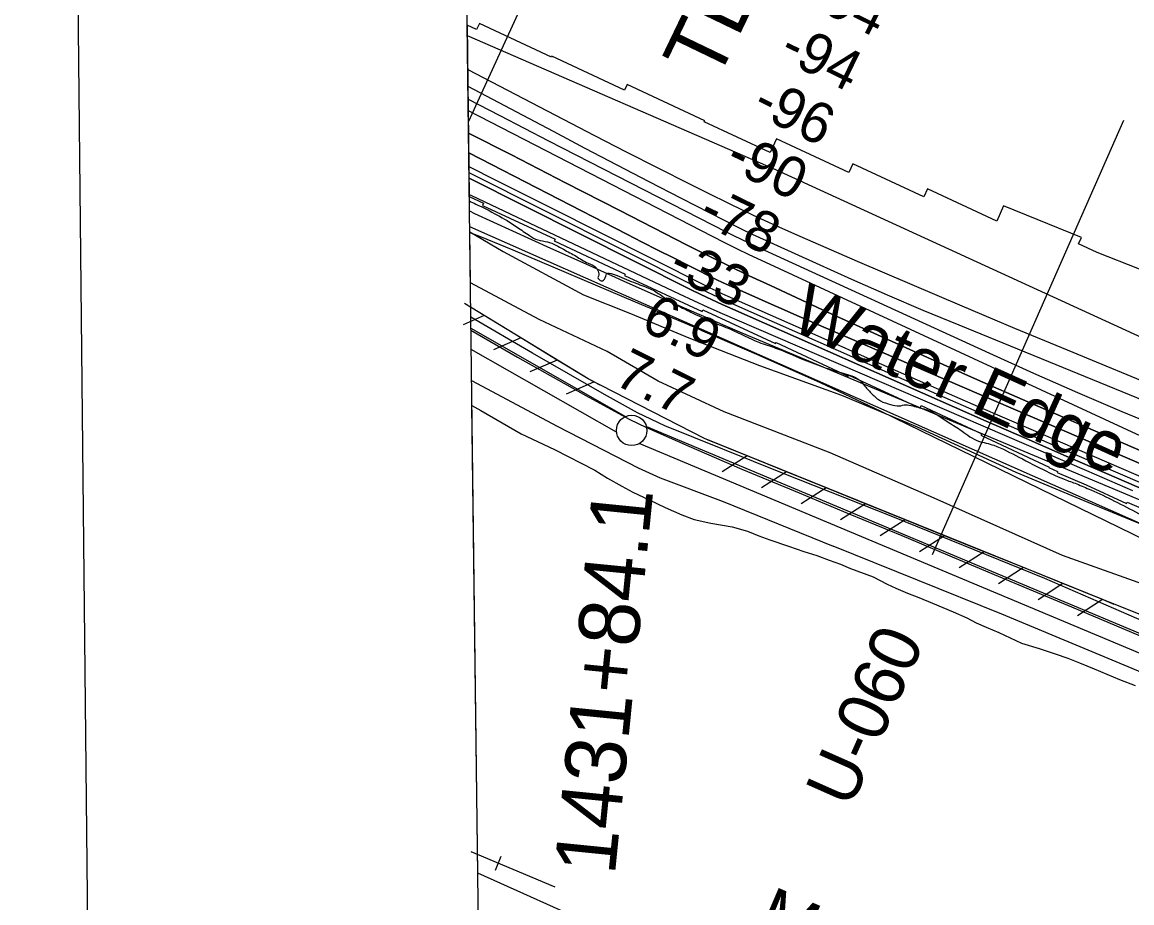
# Model space of a CAD drawing. Extents: x 3734862 to 3772949, y 391520 to 417239.
# Drawn here: x 3738202 to 3740026, y 405553 to 406999 of the extents above; entities that cross this region are included whole.
import ezdxf

# ---------------------------------------------------------------- set-up
doc = ezdxf.new("R2010")
doc.units = 0
for name, color, linetype in [('V-ANNO-SYMB', 7, 'Continuous'), ('V-CHAN-NAID', 7, 'Continuous'), ('V-FLOD-BASE', 7, 'Continuous'), ('V-GRID-FRAM', 7, 'Continuous'), ('V-LEVE-TOET', 7, 'Continuous'), ('V-RAIL-IDEN', 7, 'Continuous'), ('V-RAIL-TRAK', 7, 'Continuous'), ('V-RIVR-EDGE', 7, 'Continuous'), ('V-RIVR-IDEN', 7, 'Continuous'), ('V-RIVR-RANG', 7, 'Continuous'), ('V-RIVR-RANG-IDEN', 7, 'Continuous'), ('V-RRAP-FSHR', 7, 'Continuous'), ('V-RRAP-RVMT', 7, 'Continuous'), ('V-SITE-VEGE', 7, 'Continuous'), ('V-SURV-IDEN', 7, 'Continuous'), ('V-SURV-LINE', 7, 'Continuous'), ('V-TOPO-DPTH', 7, 'Continuous'), ('V-TOPO-MAJR', 7, 'Continuous'), ('V-TOPO-MINR', 7, 'Continuous'), ('V-TOPO-WATR', 7, 'Continuous')]:
    doc.layers.add(name, color=color, linetype=linetype)

msp = doc.modelspace()

# ---------------------------------------------------------------- linework, layer by layer
at = {"layer": 'V-ANNO-SYMB'}
msp.add_lwpolyline([(3738444.4, 392757.5), (3771525.7, 393106.9), (3771283.7, 416022.2), (3738202.3, 415672.8), (3738444.4, 392757.5)], dxfattribs=at)
at = {"layer": 'V-FLOD-BASE'}
msp.add_lwpolyline([(3738939.8, 406493.4), (3739016.1, 406448.9), (3739128.5, 406386), (3739199.5, 406346.9), (3739228.4, 406333.2), (3739297.9, 406302.6), (3739384.8, 406265.2), (3739478.9, 406226), (3739562.2, 406190.9), (3739648, 406156.1), (3739741.1, 406116.9), (3739833.6, 406077.7), (3739926.7, 406039.1), (3740025.4, 405997.5), (3740124.6, 405955.2)], dxfattribs=at)
at = {"layer": 'V-GRID-FRAM'}
msp.add_lwpolyline([(3738832.3, 415033.8), (3770599.2, 415447.4), (3770843.8, 397266.6), (3739061.1, 396852.8), (3738832.3, 415033.8)], dxfattribs=at)
at = {"layer": 'V-LEVE-TOET'}
for points in [[(3741628.7, 405352.2), (3741426.2, 405436.3), (3741222.6, 405521), (3741001.7, 405613.9), (3740778.7, 405706.8), (3740561.8, 405793.6), (3740300.3, 405903.7), (3740121.9, 405981.5), (3739882.5, 406085.3), (3739632.9, 406186.6), (3739451.9, 406258.3), (3739258.1, 406336.2), (3739213.5, 406357.5), (3739159.2, 406387.5), (3739040.8, 406455.3), (3738939.5, 406514.6)], [(3738940.8, 406410.9), (3739081.4, 406335.4), (3739214.6, 406267.1), (3739250.5, 406251), (3739354.1, 406212), (3739535.1, 406138.7)], [(3741503.1, 405309.1), (3741232, 405429.5), (3740957.7, 405546.3), (3740650.1, 405671.5), (3740361.5, 405794.5), (3740102.6, 405906.1), (3739811.9, 406027.1), (3739535.1, 406138.7)]]:
    msp.add_lwpolyline(points, dxfattribs=at)
at = {"layer": 'V-RAIL-TRAK'}
for points in [[(3739078, 405578.6), (3738939.9, 405636.7)], [(3738979.9, 405606.4), (3738989.6, 405629.4)]]:
    msp.add_lwpolyline(points, dxfattribs=at)
at = {"layer": 'V-RIVR-EDGE'}
msp.add_spline([(3738937.1, 406705.6), (3738947.7, 406700.5), (3739015.5, 406662.8), (3739036.1, 406648.6), (3739049.4, 406641.7), (3739065.6, 406638.4), (3739091.8, 406626.2), (3739112.4, 406614.8), (3739132.2, 406603.4), (3739146, 406595.3), (3739148.8, 406590.1), (3739149.2, 406582), (3739148.3, 406580), (3739150.4, 406576.7), (3739153.6, 406574.3), (3739157.6, 406575.5), (3739162.1, 406584.4), (3739163.3, 406586.4), (3739166.6, 406586.8), (3739179.9, 406583.1), (3739195.6, 406576.6), (3739210.6, 406570.5), (3739223.9, 406565.6), (3739243.7, 406556.3), (3739261.5, 406543.7), (3739278.8, 406533.9), (3739301.1, 406523), (3739336.6, 406506.7), (3739366.1, 406494.9), (3739412.9, 406473.4), (3739440.4, 406464), (3739478.8, 406448.1), (3739513.5, 406434.7), (3739547.5, 406423.7), (3739562, 406419.6), (3739576.2, 406413.1), (3739587, 406401.3), (3739599.1, 406388.4), (3739612.9, 406377), (3739629.4, 406371.3), (3739643.6, 406368.9), (3739654.1, 406370.9), (3739665.8, 406368.8), (3739687.2, 406363.1), (3739704.2, 406355.4), (3739724, 406342.4), (3739746.6, 406327.8), (3739773.6, 406311.1), (3739786.6, 406307.9), (3739798.7, 406304.2), (3739840.3, 406284.7), (3739885.5, 406261.5), (3739914.6, 406248.5), (3739935.2, 406240.8), (3739958.2, 406231), (3739997.4, 406212.7), (3740036.6, 406192.4), (3740070.1, 406176.1), (3740091.9, 406166), (3740122.6, 406155), (3740144.9, 406150.5), (3740162.6, 406145.6), (3740180.8, 406138.7), (3740205.9, 406128.9), (3740242.6, 406112.6), (3740284.2, 406091.5)], degree=3, dxfattribs=at)
at = {"layer": 'V-RIVR-RANG'}
for p, q in [((3738935.5, 406835.4), (3739084.1, 407158.7)), ((3739697.9, 406124.6), (3740012.4, 406838.4))]:
    msp.add_line(p, q, dxfattribs=at)
at = {"layer": 'V-RRAP-FSHR'}
for p, q in [((3738961.7, 406517.2), (3738927, 406501.9)), ((3739021.5, 406480.7), (3738976.8, 406461.1)), ((3739081.3, 406444.3), (3739036.6, 406424.7)), ((3739141.1, 406407.9), (3739096.3, 406388.3)), ((3739393.4, 406286.9), (3739352.4, 406260.4)), ((3739458.3, 406260.7), (3739417.3, 406234.1)), ((3739523.2, 406234.5), (3739482.2, 406207.9)), ((3739588.1, 406208.2), (3739547.1, 406181.7)), ((3739653, 406182), (3739612, 406155.4)), ((3739717.9, 406155.8), (3739676.9, 406129.2)), ((3739782.8, 406129.5), (3739741.8, 406103)), ((3739847.7, 406103.3), (3739806.7, 406076.7)), ((3739912.6, 406077.1), (3739871.6, 406050.5)), ((3739977.5, 406050.8), (3739936.5, 406024.3))]:
    msp.add_line(p, q, dxfattribs=at)
for points in [[(3738937.6, 406663.6), (3740052.6, 406170.3), (3741469, 405553.1)], [(3740004.8, 406039.8), (3739323.4, 406315.2), (3739132.3, 406413.3), (3738929, 406537.1)], [(3738961.7, 406517.2), (3738929, 406537.1)], [(3739021.5, 406480.7), (3738961.7, 406517.2)], [(3739081.3, 406444.3), (3739021.5, 406480.7)], [(3739141.4, 406408.6), (3739132.3, 406413.3), (3739081.3, 406444.3)], [(3739151.9, 406403.2), (3739141.4, 406408.6)], [(3739328.5, 406313.2), (3739323.4, 406315.2), (3739318, 406318)], [(3739393.4, 406286.9), (3739328.5, 406313.2)], [(3739458.3, 406260.7), (3739393.4, 406286.9)], [(3739523.2, 406234.5), (3739458.3, 406260.7)], [(3739588.1, 406208.2), (3739523.2, 406234.5)], [(3739653, 406182), (3739588.1, 406208.2)], [(3739717.9, 406155.8), (3739653, 406182)], [(3739782.8, 406129.5), (3739717.9, 406155.8)], [(3739847.7, 406103.3), (3739782.8, 406129.5)], [(3739912.6, 406077.1), (3739847.7, 406103.3)], [(3739977.5, 406050.8), (3739912.6, 406077.1)], [(3739996.9, 406043), (3739977.5, 406050.8)], [(3744483.7, 404317.7), (3744096.9, 404414.5), (3743639.2, 404531), (3743120.2, 404667), (3742731.1, 404762.5), (3742601.7, 404809.4), (3742448.9, 404910.7), (3742129.5, 405108.3), (3741905.3, 405240.5), (3741772.8, 405307.9), (3741598.8, 405383.1), (3741291.5, 405502.3), (3740610.8, 405791.5), (3740295.5, 405923.9), (3740004.8, 406039.8)]]:
    msp.add_lwpolyline(points, dxfattribs=at)
at = {"layer": 'V-RRAP-RVMT'}
for p, q in [((3738953.6, 406996.9), (3738949, 406987.1)), ((3739072.1, 406941.7), (3738953.6, 406996.9)), ((3738933.5, 406994.3), (3738937, 406712.7)), ((3738949, 406987.1), (3738933.5, 406994.3)), ((3739072.9, 406943.5), (3739072.1, 406941.7)), ((3739192.3, 406887.8), (3739072.9, 406943.5)), ((3739196.4, 406896.8), (3739192.3, 406887.8)), ((3739323.9, 406837.4), (3739196.4, 406896.8)), ((3739323, 406835.6), (3739323.9, 406837.4)), ((3739431.6, 406785), (3739323, 406835.6)), ((3739442, 406807.4), (3739431.6, 406785)), ((3739560.5, 406752.2), (3739442, 406807.4)), ((3739567.2, 406766.5), (3739560.5, 406752.2)), ((3739683.9, 406712.3), (3739567.2, 406766.5)), ((3739690.1, 406725.6), (3739683.9, 406712.3)), ((3739803.9, 406672.6), (3739690.1, 406725.6)), ((3738937, 406712.7), (3738960.3, 406701.9)), ((3738960.3, 406701.9), (3738958.6, 406698.2)), ((3738958.6, 406698.2), (3739078, 406642.6)), ((3739814.6, 406697.7), (3739803.9, 406672.6)), ((3739942.9, 406645.5), (3739814.6, 406697.7)), ((3739078, 406642.6), (3739076.7, 406639.9)), ((3739076.7, 406639.9), (3739193.4, 406585.5)), ((3739938.2, 406635.1), (3739942.9, 406645.5)), ((3739968.7, 406620.9), (3739938.2, 406635.1)), ((3740038.2, 406593.6), (3739968.7, 406620.9)), ((3739193.4, 406585.5), (3739192.3, 406583.3)), ((3739192.3, 406583.3), (3739319.6, 406523.9)), ((3739319.6, 406523.9), (3739321, 406526.8)), ((3739321, 406526.8), (3739440.2, 406471.3)), ((3739440.2, 406471.3), (3739441.1, 406473.2)), ((3739441.1, 406473.2), (3739559.8, 406417.9)), ((3739559.8, 406417.9), (3739560.6, 406419.6)), ((3739560.6, 406419.6), (3739677.7, 406365.1)), ((3739677.7, 406365.1), (3739679.8, 406369.5)), ((3739679.8, 406369.5), (3739779, 406323.3)), ((3739779, 406323.3), (3739777.8, 406320.8)), ((3739777.8, 406320.8), (3739890.1, 406268.5)), ((3739890.1, 406268.5), (3739889.6, 406267.6)), ((3739889.6, 406267.6), (3739903.8, 406261)), ((3739903.8, 406261), (3739903, 406259.3)), ((3739903, 406259.3), (3739950.6, 406239.2)), ((3739950.6, 406239.2), (3740016.7, 406208.4)), ((3740016.7, 406208.4), (3740017.8, 406210.8)), ((3740017.8, 406210.8), (3740063.1, 406191.6))]:
    msp.add_line(p, q, dxfattribs=at)
at = {"layer": 'V-SITE-VEGE'}
for p, q in [((3738938.8, 406571.2), (3738937.7, 406655)), ((3738937.7, 406655), (3738992.7, 406622.6)), ((3738992.7, 406622.6), (3739124.7, 406551.2)), ((3739052, 406511.1), (3738938.8, 406571.2)), ((3739124.7, 406551.2), (3739201.7, 406520.6)), ((3739163.4, 406458.2), (3739052, 406511.1)), ((3739201.7, 406520.6), (3739297.7, 406480.8)), ((3739297.7, 406480.8), (3739414, 406435.1)), ((3739247.4, 406409.5), (3739163.4, 406458.2)), ((3739414, 406435.1), (3739548.9, 406386.8)), ((3739356, 406359.2), (3739247.4, 406409.5)), ((3739548.9, 406386.8), (3739673.1, 406334.8)), ((3738951, 405601.4), (3738941.3, 406369.6)), ((3738941.3, 406369.6), (3738956.2, 406361.6)), ((3738956.2, 406361.6), (3738990.8, 406341.1)), ((3739530.1, 406291.6), (3739356, 406359.2)), ((3738990.8, 406341.1), (3739022, 406322.8)), ((3739022, 406322.8), (3739077.1, 406297.2)), ((3739673.1, 406334.8), (3739835.1, 406259.9)), ((3739077.1, 406297.2), (3739143.4, 406263.4)), ((3739700.9, 406217.3), (3739530.1, 406291.6)), ((3739143.4, 406263.4), (3739163.9, 406250.3)), ((3739163.9, 406250.3), (3739187.4, 406236.9)), ((3739835.1, 406259.9), (3739959.9, 406208)), ((3739187.4, 406236.9), (3739205.7, 406227.3)), ((3739205.7, 406227.3), (3739232.6, 406214.5)), ((3739232.6, 406214.5), (3739258.6, 406202.3)), ((3739912, 406123.1), (3739700.9, 406217.3)), ((3739258.6, 406202.3), (3739286, 406190.2)), ((3739959.9, 406208), (3740080.6, 406158.5)), ((3739286, 406190.2), (3739306.6, 406182.4)), ((3739306.6, 406182.4), (3739333.8, 406176.4)), ((3739333.8, 406176.4), (3739369.1, 406170.1)), ((3739369.1, 406170.1), (3739394.2, 406163)), ((3739394.2, 406163), (3739412.7, 406155.6)), ((3739412.7, 406155.6), (3739430.6, 406149)), ((3739430.6, 406149), (3739461.4, 406138.7)), ((3739461.4, 406138.7), (3739487, 406129.9)), ((3739487, 406129.9), (3739508.2, 406123)), ((3739508.2, 406123), (3739528.6, 406115.7)), ((3740099.9, 406056), (3739912, 406123.1)), ((3739528.6, 406115.7), (3739546.9, 406108.8)), ((3739546.9, 406108.8), (3739563.4, 406101.7)), ((3739563.4, 406101.7), (3739600.5, 406088.4)), ((3739600.5, 406088.4), (3739623.8, 406076.3)), ((3739623.8, 406076.3), (3739638, 406069.7)), ((3739638, 406069.7), (3739657, 406061.4)), ((3739657, 406061.4), (3739675.6, 406054.3)), ((3739675.6, 406054.3), (3739698.4, 406044.7)), ((3739698.4, 406044.7), (3739731.9, 406030.9)), ((3739731.9, 406030.9), (3739754.7, 406020.9)), ((3739754.7, 406020.9), (3739769.9, 406012.9)), ((3739769.9, 406012.9), (3739786.4, 406005.3)), ((3739786.4, 406005.3), (3739807, 405996.6)), ((3739807, 405996.6), (3739844.3, 405979.5)), ((3739844.3, 405979.5), (3739873.2, 405970.7)), ((3739873.2, 405970.7), (3739899.5, 405961.8)), ((3739899.5, 405961.8), (3739920.3, 405954.4)), ((3739920.3, 405954.4), (3739939.8, 405946.9)), ((3739939.8, 405946.9), (3739964, 405937.2)), ((3739964, 405937.2), (3740005.3, 405919.6)), ((3740005.3, 405919.6), (3740031.1, 405909.5)), ((3739168, 405504.4), (3738951, 405601.4))]:
    msp.add_line(p, q, dxfattribs=at)
at = {"layer": 'V-SURV-LINE'}
for points in [[(3738939.7, 406496.5), (3739193.9, 406351.7)], [(3739179, 406325.6), (3738940.2, 406461.7)], [(3739228, 406334.9), (3740657.2, 405736.1)], [(3740645.7, 405708.4), (3739216.4, 406307.2)]]:
    msp.add_lwpolyline(points, dxfattribs=at)
msp.add_circle((3739203.8, 406328.7), 25, dxfattribs=at)
at = {"layer": 'V-TOPO-DPTH'}
for points in [[(3740184.8, 406232.5), (3739854.6, 406375.8), (3739772.1, 406412), (3739689.8, 406448.5), (3739607.7, 406485.6), (3739525.7, 406523.1), (3739431.7, 406566.5), (3739397, 406582.7), (3739362.5, 406599.3), (3739328.1, 406616.3), (3739294, 406633.6), (3739184.3, 406690), (3739095.3, 406735.6), (3739006.3, 406781.2), (3738935.7, 406817.1)], [(3740184.8, 406232.5), (3739854.6, 406375.8), (3739772.1, 406412), (3739689.8, 406448.5), (3739607.7, 406485.6), (3739525.7, 406523.1), (3739431.7, 406566.5), (3739397, 406582.7), (3739362.5, 406599.3), (3739328.1, 406616.3), (3739294, 406633.6), (3739184.3, 406690), (3739095.3, 406735.6), (3739006.3, 406781.2), (3738935.7, 406817.1)], [(3740158.1, 406222.6), (3739475.1, 406517.5), (3739454.2, 406526.7), (3739433.2, 406535.8), (3739412.3, 406545.1), (3739391.4, 406554.4), (3739354.2, 406571), (3739351.9, 406572.1), (3739349.6, 406573.1), (3739347.3, 406574.2), (3739345.1, 406575.3), (3739298.2, 406598.9), (3739272.5, 406611.9), (3739246.9, 406624.9), (3739221.3, 406637.9), (3739195.7, 406651), (3738936.1, 406784.4)], [(3738936.1, 406784.4), (3739195.7, 406651), (3739221.3, 406637.9), (3739246.9, 406624.9), (3739272.5, 406611.9), (3739298.2, 406598.9), (3739345.1, 406575.3), (3739347.3, 406574.2), (3739349.6, 406573.1), (3739351.9, 406572.1), (3739354.2, 406571), (3739391.4, 406554.4), (3739412.3, 406545.1), (3739433.2, 406535.8), (3739454.2, 406526.7), (3739475.1, 406517.5), (3740158.1, 406222.6)], [(3738936.4, 406762.2), (3738980.6, 406739.8), (3739069.2, 406695.2), (3739322.8, 406567.8), (3739332.5, 406563), (3739342.3, 406558.3), (3739352.2, 406553.8), (3739362.1, 406549.3), (3739514.4, 406481.6), (3739600.5, 406443.6), (3739686.8, 406405.7), (3739773.2, 406368.1), (3739859.6, 406330.7), (3740132.5, 406213.1)], [(3738936.4, 406762.2), (3738980.6, 406739.8), (3739069.2, 406695.2), (3739322.8, 406567.8), (3739332.5, 406563), (3739342.3, 406558.3), (3739352.2, 406553.8), (3739362.1, 406549.3), (3739514.4, 406481.6), (3739600.5, 406443.6), (3739686.8, 406405.7), (3739773.2, 406368.1), (3739859.6, 406330.7), (3740132.5, 406213.1)], [(3740049.9, 406229.2), (3739983.9, 406257.7), (3739918, 406286.4), (3739852.1, 406315.2), (3739786.4, 406344.1), (3739370, 406527.6), (3739352.5, 406535.5), (3739335, 406543.5), (3739317.7, 406551.9), (3739300.5, 406560.3), (3738936.6, 406742.8)], [(3740049.9, 406229.2), (3739983.9, 406257.7), (3739918, 406286.4), (3739852.1, 406315.2), (3739786.4, 406344.1), (3739370, 406527.6), (3739352.5, 406535.5), (3739335, 406543.5), (3739317.7, 406551.9), (3739300.5, 406560.3), (3738936.6, 406742.8)], [(3738937.3, 406689.1), (3738945.8, 406685.2), (3739008.2, 406656.6), (3739070.7, 406628.1), (3739133.3, 406599.9), (3739196, 406571.8), (3739258.6, 406543.9), (3739290.1, 406530), (3739321.6, 406516.2), (3739353.2, 406502.6), (3739384.9, 406489.2), (3740110.7, 406184.8)]]:
    msp.add_lwpolyline(points, dxfattribs=at)
at = {"layer": 'V-TOPO-MAJR'}
msp.add_lwpolyline([(3738935.2, 406854.1), (3739336.2, 406647.6), (3739356.2, 406637.4), (3739376.3, 406627.5), (3739396.5, 406617.7), (3739416.8, 406608.2), (3740092.1, 406295.7)], dxfattribs=at)
at = {"layer": 'V-TOPO-MINR'}
for points in [[(3738933.7, 406977.3), (3739440.1, 406757), (3740227.3, 406396.2), (3740253.6, 406384.2), (3740280, 406372.5), (3740306.5, 406361), (3740333.1, 406349.6), (3740460.9, 406295.8), (3740551.4, 406257.7), (3740642, 406219.7), (3740732.6, 406181.7), (3740823.2, 406143.8), (3741080.5, 406036.5), (3741091.8, 406031.7), (3741103.2, 406027), (3741114.5, 406022.3), (3741125.8, 406017.6), (3741393.9, 405906.1), (3741487.4, 405867.5), (3741581, 405829.2), (3741674.8, 405791.5), (3741768.7, 405754), (3741888.2, 405706.7)], [(3738934.4, 406921.5), (3739091.3, 406839.9), (3739143, 406813.2), (3739194.8, 406786.5), (3739246.7, 406760), (3739298.7, 406733.7), (3739327.3, 406719.3), (3739365.2, 406700.6), (3739403.3, 406682.3), (3739441.7, 406664.8), (3739480.3, 406647.6), (3739574.5, 406606.8), (3739660.4, 406569.9), (3739746.5, 406533.2), (3739832.8, 406496.9), (3739919.2, 406461), (3740242.8, 406327.2)], [(3738934.7, 406894), (3739074.6, 406820), (3739127, 406792.4), (3739179.6, 406764.9), (3739232.2, 406737.6), (3739284.9, 406710.4), (3739379.5, 406661.9), (3739385, 406659.1), (3739390.5, 406656.3), (3739396.1, 406653.7), (3739401.7, 406651.1), (3739506.8, 406603.2), (3739565.2, 406577.1), (3739623.7, 406551.4), (3739682.5, 406526.4), (3739741.6, 406501.9), (3740204.8, 406312.7)], [(3738935, 406873), (3738987.1, 406845.9), (3739067.2, 406804.6), (3739358.9, 406655), (3739371.3, 406648.8), (3739383.8, 406642.6), (3739396.3, 406636.6), (3739408.9, 406630.8), (3739791.7, 406455.3), (3739864, 406422.8), (3739936.6, 406390.8), (3740009.5, 406359.9), (3740082.8, 406329.5)], [(3738935.7, 406817.1), (3739006.3, 406781.2), (3739095.3, 406735.6), (3739184.3, 406690), (3739294, 406633.6), (3739328.1, 406616.3), (3739362.5, 406599.3), (3739397, 406582.7), (3739431.7, 406566.5), (3739525.7, 406523.1), (3739607.7, 406485.6), (3739689.8, 406448.5), (3739772.1, 406412), (3739854.6, 406375.8), (3740184.8, 406232.5)], [(3738936.1, 406784.4), (3739195.7, 406651), (3739221.3, 406637.9), (3739246.9, 406624.9), (3739272.5, 406611.9), (3739298.2, 406598.9), (3739345.1, 406575.3), (3739347.3, 406574.2), (3739349.6, 406573.1), (3739351.9, 406572.1), (3739354.2, 406571), (3739391.4, 406554.4), (3739412.3, 406545.1), (3739433.2, 406535.8), (3739454.2, 406526.7), (3739475.1, 406517.5), (3740158.1, 406222.6)], [(3738936.4, 406762.2), (3738980.6, 406739.8), (3739069.2, 406695.2), (3739322.8, 406567.8), (3739332.5, 406563), (3739342.3, 406558.3), (3739352.2, 406553.8), (3739362.1, 406549.3), (3739514.4, 406481.6), (3739600.5, 406443.6), (3739686.8, 406405.7), (3739773.2, 406368.1), (3739859.6, 406330.7), (3740132.5, 406213.1)], [(3738936.5, 406752.4), (3739311.7, 406564.1), (3739325.1, 406557.4), (3739338.7, 406550.9), (3739352.3, 406544.6), (3739366, 406538.4), (3739614.9, 406428.3), (3739709.8, 406386.5), (3739804.8, 406344.9), (3739900, 406303.5), (3739995.2, 406262.3), (3740159.5, 406191.6)], [(3738936.6, 406742.8), (3739300.5, 406560.3), (3739317.7, 406551.9), (3739335, 406543.5), (3739352.5, 406535.5), (3739370, 406527.6), (3739786.4, 406344.1), (3739852.1, 406315.2), (3739918, 406286.4), (3739983.9, 406257.7), (3740049.9, 406229.2)], [(3738937, 406716.4), (3738940.6, 406714.7), (3739026.2, 406674), (3739281.8, 406553.1), (3739305.4, 406542.2), (3739329, 406531.3), (3739352.8, 406520.7), (3739376.6, 406510.3), (3739951.2, 406262.6), (3739989, 406246.3), (3740026.8, 406230)], [(3738937.8, 406653.8), (3738953.9, 406647.5), (3739008.3, 406625.3), (3739209.5, 406540.1), (3739226.6, 406532.8), (3739243.6, 406525.5), (3739260.7, 406518.2), (3739277.7, 406510.9), (3739303.2, 406499.9), (3739307.5, 406498.1), (3739311.8, 406496.2), (3739316.1, 406494.4), (3739320.3, 406492.5), (3739412.9, 406452.3), (3739463.3, 406430), (3739513.6, 406407.3), (3739563.5, 406383.9), (3739613.2, 406360.1), (3740092.1, 406126.8)]]:
    msp.add_lwpolyline(points, dxfattribs=at)
at = {"layer": 'V-TOPO-WATR'}
msp.add_lwpolyline([(3738937.3, 406689.1), (3738945.8, 406685.2), (3739008.2, 406656.6), (3739070.7, 406628.1), (3739133.3, 406599.9), (3739196, 406571.8), (3739258.6, 406543.9), (3739290.1, 406530), (3739321.6, 406516.2), (3739353.2, 406502.6), (3739384.9, 406489.2), (3740110.7, 406184.8)], dxfattribs=at)

# ---------------------------------------------------------------- texts
at = {"layer": 'V-CHAN-NAID'}
msp.add_text('TECO BULK NO. 2 (55.4)', height=100, rotation=64.2775, dxfattribs=at).set_placement((3739342.8, 406898.2))
at = {"layer": 'V-RAIL-IDEN'}
msp.add_text('MO.    PAC.', height=83, rotation=336.7726, dxfattribs=at).set_placement((3739404.3, 405504.4))
at = {"layer": 'V-RIVR-IDEN'}
msp.add_text('Water Edge', height=83, rotation=335.6313, dxfattribs=at).set_placement((3739460.7, 406495.6))
at = {"layer": 'V-RIVR-RANG'}
for s, rotation, p in [('-94', 333.9499, (3739487.6, 407030.4)), ('-94', 333.9499, (3739443.5, 406940.7)), ('-96', 333.9499, (3739399.1, 406851.1)), ('-90', 333.9499, (3739354.3, 406761.7)), ('-78', 333.9499, (3739309.9, 406672.1)), ('-33', 333.9499, (3739260.5, 406584.9)), ('6.9', 333.6683, (3739216, 406495.8)), ('7.7', 333.6683, (3739172.1, 406406))]:
    msp.add_text(s, height=67, rotation=rotation, dxfattribs=at).set_placement(p)
at = {"layer": 'V-RIVR-RANG-IDEN'}
msp.add_text('U-060', height=83, rotation=66.0823, dxfattribs=at).set_placement((3739563.3, 405705.9))
at = {"layer": 'V-SURV-IDEN'}
msp.add_text('1431+84.1', height=100, rotation=84.2936, dxfattribs=at).set_placement((3739176.1, 405596.7))

doc.saveas('drawing.dxf')
